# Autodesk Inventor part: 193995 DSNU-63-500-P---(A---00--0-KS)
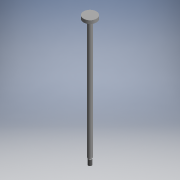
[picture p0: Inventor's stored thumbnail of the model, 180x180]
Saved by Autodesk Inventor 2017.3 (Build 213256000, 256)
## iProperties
Part Number: 193995 DSNU-63-500-P---(A---00--0-KS)
Material: Generic
Catalog Web Link: www.cadenas.de
Description: DSNU---(KS)-Standard cylinder
Vendor: FESTO
Document SubType Name: Modeling
Designer: partserver
Manufacturer: FESTO
Mass: 238.989 g
Surface Area: 477.097 cm^2
Volume: 238.989 cm^3
Density: 1 g/cm^3
Appearance: PSOLRGB-192-192-192
Category: PARTsolutions
Company: FESTO
Title: 193995 DSNU-63-500-P
Author: Cadenas PARTsolutions
Comments: Standard cylinder
PSOL_IDENT_0: {$CADENAS_DATA\23d-libs\festo\parts\d\dsnu\parts\dsnu_metric_ks.prj},257 {VTYP=3D},{NB=193995 DSNU-6
PSOL_IDENT_1: 3-500-P---(A---00--0-KS)},{LINA=193995 DSNU-63-500-P},{NN=DSNU---(KS)},{DATE=01.06.2021 12:08:39},{G
PSOL_IDENT_2: EOMDATE=06.03.2020 09:03:14},{VERSION=},{LINEID=100},{WBVAR=TNR,HUB,DA,PE,ZD,VS,KA,K2A,K6,K3,K5,K8,K
PSOL_IDENT_3: P},{WBNUMERIC=HUB,K2A,K6,K8}  {NB=193995 DSNU-63-500-P---(A---00--0-KS)},{LINA=193995 DSNU-63-500-P}
PSOL_IDENT_4: ,{KT=DUMMY},{TNR=193995},{TYP=DSNU-63},{DSNU=METRIC},{KDM=63},{HUB=500},{DA=P},{DA1='P','PPV','PPS'}
PSOL_IDENT_5: ,{PE=A},{ZD=-},{VS=-},{VSALG='-','Q'},{KA=-},{KAALG='-','S2'},{K2A=0},{K6=0},{K3=-},{K31='-','K3'},{
PSOL_IDENT_6: K5=-},{K51='-','M16'},{K8=0},{KP=-},{KPALG='-','KP'},{A1=70},{A2=500},{A3=10},{A4=87.5},{AB=44},{AM=
PSOL_IDENT_7: 32},{B=45},{BB=4},{BE=M45x1,5},{BENDM=45.000},{BEKDM=43.160},{BEP=1.500},{BS=11.0},{B1=72},{B2=17},{
PSOL_IDENT_8: B3=44},{B4=15},{B5=36.0},{B6=18},{B7=4},{CD=16},{D=70},{D1=45},{D2=20},{D3=65.4},{D4=16.0},{D5=66.0}
PSOL_IDENT_9: ,{D6=60},{D7=45},{EE=G3/8},{EENDM=16.662},{EEKDM=14.950},{EW=21},{F=52},{FF=M8},{FFNDM=8.000},{FFKDM=
PSOL_IDENT_10: 6.466},{F1=36},{H=72},{H1=8},{KK=M16x1.5},{KKNDM=16.000},{KKKDM=0.000},{KKP=1.500},{K1=M10},{K1NDM=1
PSOL_IDENT_11: 0.000},{K1KDM=8.160},{K2=3.5},{KV=0},{KW=10},{L=16},{LH=15.0},{LK=28.0},{L1=172.2},{L2=94.2},{L3=13.
PSOL_IDENT_12: 0},{L4=33.0},{L5=30},{L6=77},{L7=44},{L8=28.0},{L9=32.0},{L10=117.2},{L11=132.2},{L12=94.2},{L13=184
PSOL_IDENT_13: .2},{ST=11.0},{SW=17},{T=16},{WH=45},{X=4.7},{XC=156.2},{K1KP=72},{K2KP=M10},{K2KPNDM=10.000},{K3KP=
PSOL_IDENT_14: 21},{K4KP=36.0},{K5KP=121.5},{K6KP=8.5},{K7KP=38},{K8KP=54.0},{K9KP=24.0},{K10KP=8.0},{K11KP=32},{K1
PSOL_IDENT_15: 2KP=G1/8},{K12KPNDM=9.728},{K13KP=86},{ZRSTART=61},{MHL=51.000},{ZRL=38.2},{C=25.200},{WHX=15.000},{
PSOL_IDENT_16: LD1=42.800},{LD2=42.800},{AD1=17.000},{AD2=13.000},{AD3=17.000},{AD4=13.000},{AD5=13.000},{MH1=14.00
PSOL_IDENT_17: 0},{MH2=3.100},{MH3=20.200},{KP1=48.000},{KP2=33.000},{KP3=25.000},{KP4=40.000},{KP5=50.000},{KPC=36
PSOL_IDENT_18: .000},{KPF=3.000},{KPG=30.000},{KPH=115.500},{KPJ=37.500},{KPK=17.000},{KPL=6.000},{KPR3=1.500},{KPR=
PSOL_IDENT_19: 37.000},{KPS=28.500},{MLD1=62.000},{MLD2=58.000},{MLD3=5.000},{MLL1=18.000},{KL1=85.2},{KKC=13.9},{K
PSOL_IDENT_20: KD=2.6},{KKF=0.75},{SWL=8.000},{K3L=10.500},{HUB1=500},{FDTXF31=6.000},{FDTB31=8.000}
NB: 193995 DSNU-63-500-P---(A---00--0-KS)
NN: DSNU---(KS)
NT: Standard cylinder
NBSYN: $TNR. $TYP.-$HUB1.-$DA.---($PE.$ZD.$VS.$KA.$K2A.$K6.$K3.$K5.$K8.$KP.KS)
LINA: 193995 DSNU-63-500-P
CATALOG: Festo
TNR: 193995
TYP: DSNU-63
DSNU: METRIC
KDM: 63
HUB: 500
DA: P
DA1: 'P','PPV','PPS'
PE: A
ZD: -
VS: -
KA: -
K2A: 0
K6: 0
K3: -
K31: '-','K3'
K5: -
K51: '-','M16'
K8: 0
KP: -
A1: 70
A2: 500
A3: 10
A4: 87.5
AB: 44
AM: 32
B: 45
BB: 4
BE: M45x1,5
BENDM: 45
BEKDM: 43.16
BEP: 1.5
BS: 11
B1: 72
B2: 17
B3: 44
B4: 15
B5: 36
B6: 18
B7: 4
CD: 16
D: 70
D1: 45
D2: 20
D3: 65.4
D4: 16
D5: 66
D6: 60
D7: 45
EE: G3/8
EENDM: 16.662
EEKDM: 14.95
EW: 21
F: 52
FF: M8
FFNDM: 8
FFKDM: 6.466
F1: 36
H: 72
H1: 8
KK: M16x1.5
KKNDM: 16
KKKDM: 0
KKP: 1.5
K1: M10
K1NDM: 10
K1KDM: 8.16
K2: 3.5
KV: 0
KW: 10
L: 16
LH: 15
LK: 28
L3: 13
L4: 33
L5: 30
L6: 77
L7: 44
L8: 28
L9: 32
L13: 184.2
ST: 11
SW: 17
T: 16
X: 4.7
K1KP: 72
K2KP: M10
K2KPNDM: 10
K3KP: 21
K4KP: 36
K5KP: 121.5
K6KP: 8.5
K7KP: 38
K8KP: 54
K9KP: 24
K10KP: 8
K11KP: 32
K12KP: G1/8
K12KPNDM: 9.728
K13KP: 86
MHL: 51
C: 25.2
WHX: 15
LD1: 42.8
LD2: 42.8
AD1: 17
AD2: 13
AD3: 17
AD4: 13
AD5: 13
MH1: 14
MH2: 3.1
MH3: 20.2
KP1: 48
KP2: 33
KP3: 25
KP4: 40
KP5: 50
KPC: 36
KPF: 3
KPG: 30
KPH: 115.5
KPJ: 37.5
KPK: 17
KPL: 6
KPR3: 1.5
KPR: 37
KPS: 28.5
MLD1: 62
MLD2: 58
MLD3: 5
MLL1: 18
SWL: 8
K3L: 10.5
FDTXF31: 6
FDTB31: 8
SUPPLIER: FESTO
ARTICLENO: 193995 DSNU-63-500-P---(A---00--0-KS)
BOMINFO: 193995 DSNU-63-500-P
CREATOR: CADENAS GmbH
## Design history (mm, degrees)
sketch "Sketch_2"
  geometry: L1 (0, -588.95)-(0, 12); L2 (0, 12)-(10, 12); L3 (10, 12)-(10, -573.2); L4 (10, -573.2)-(31.5, -573.2); L5 (31.5, -573.2)-(31.5, -588.95); L6 (31.5, -588.95)-(0, -588.95); L7 (0, -588.95)-(0, 12)
  constraints: 14 end point
revolve "Revolution1" sketch "Sketch_2" stored, may be unused: angle "d0" = 360 deg
sketch "Sketch_6"
  geometry: L1 (0, 11)-(0, 44); L2 (0, 44)-(7.08, 44); L3 (7.08, 44)-(8, 43.08); L4 (8, 43.08)-(8, 17.485); L5 (8, 17.485)-(6.995, 14.724); L6 (6.95, 14.468)-(6.95, 12.75); L7 (7.7, 12)-(8, 12); L8 (8, 12)-(8, 11); L9 (8, 11)-(0, 11); L10 (0, 11)-(0, 44); A1 r 0.75 centre (7.7, 14.468) between (6.995, 14.724) and (6.95, 14.468); A2 r 0.75 centre (7.7, 12.75) between (6.95, 12.75) and (7.7, 12)
  constraints: 20 end point, 4 point on circle, 2 centre point
revolve "Revolution2" sketch "Sketch_6" stored, may be unused: angle "d1" = 360 deg
thread "Thread1" dims "d2" = 25.5951, "d3" = 0
sketch "Sketch_7"
  geometry: L1 (-17, 34)-(-17, -17); L2 (-17, -17)-(-8.5, -17); L3 (-8.5, -17)-(-8.5, 17); L4 (-8.5, 17)-(8.5, 17); L5 (8.5, 17)-(8.5, -17); L6 (8.5, -17)-(17, -17); L7 (17, -17)-(17, 34); L8 (17, 34)-(-17, 34)
  constraints: 16 end point
extrude "Extrusion1" cut sketch "Sketch_7" distance "d4" = 9; taper "d5" = 0 deg
node "FDT_KSAUFSATZ_XY"
node "FDT_KSAUFSATZ_YZ"
node "FDT_KSAUFSATZ_ZX"
node "FDT_KSAUFSATZ_X"
node "FDT_KSAUFSATZ_Y"
node "FDT_KSAUFSATZ_Z"
node "FDT_KSAUFSATZ_Center"
node "FDT_NUT_XY"
node "FDT_NUT_YZ"
node "FDT_NUT_ZX"
node "FDT_NUT_X"
node "FDT_NUT_Y"
node "FDT_NUT_Z"
node "FDT_NUT_Center"
node "KS_XY"
node "KS_YZ"
node "KS_ZX"
node "KS_X"
node "KS_Y"
node "KS_Z"
node "KS_Center"
node "NUT1_XY"
node "NUT1_YZ"
node "NUT1_ZX"
node "NUT1_X"
node "NUT1_Y"
node "NUT1_Z"
node "NUT1_Center"
body "Solid1"
